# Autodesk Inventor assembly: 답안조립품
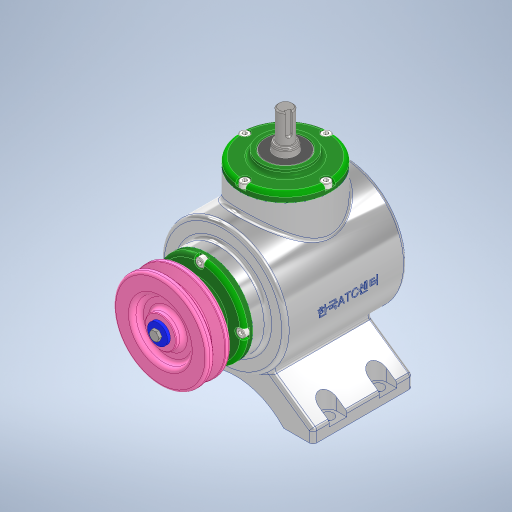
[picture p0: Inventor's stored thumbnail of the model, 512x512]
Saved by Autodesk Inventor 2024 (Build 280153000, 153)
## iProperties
Created: 2023-08
Part Number: 답안조립품
Document SubType Name: Assembly
Designer: Owner
Author: Owner
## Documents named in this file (17)
- C:\Users\Owner\Desktop\730813V1015\답안조립품.iam
- C:\Users\Owner\Desktop\730813V1015\본체.ipt
- C:\Users\Owner\Desktop\730813V1015\V-벨트풀리.ipt
- C:\Users\Owner\Desktop\730813V1015\메인 베벨기어.ipt
- C:\Users\Owner\Desktop\730813V1015\메인 축.ipt
- 메인 축.ipt
- C:\Users\Owner\Desktop\730813V1015\베어링 6203.ipt
- C:\Users\Owner\Desktop\730813V1015\볼트 M4 x 10.ipt
- C:\Users\Owner\Desktop\730813V1015\서브 베벨기어.ipt
- C:\Users\Owner\Desktop\730813V1015\서브 축.ipt
- 서브 축.ipt
- C:\Users\Owner\Desktop\730813V1015\오일실 17 x 32 x 8.ipt
- C:\Users\Owner\Desktop\730813V1015\와셔 4 x 16.ipt
- C:\Users\Owner\Desktop\730813V1015\육각볼트 M4 x 8.ipt
- C:\Users\Owner\Desktop\730813V1015\커버.ipt
- C:\Users\Owner\Desktop\730813V1015\키 4 x 4 x 14.ipt
- C:\Users\Owner\Desktop\730813V1015\키 5 x 5 x 14.ipt
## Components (1 placed, 1 different names)
1. V-벨트풀리:1
